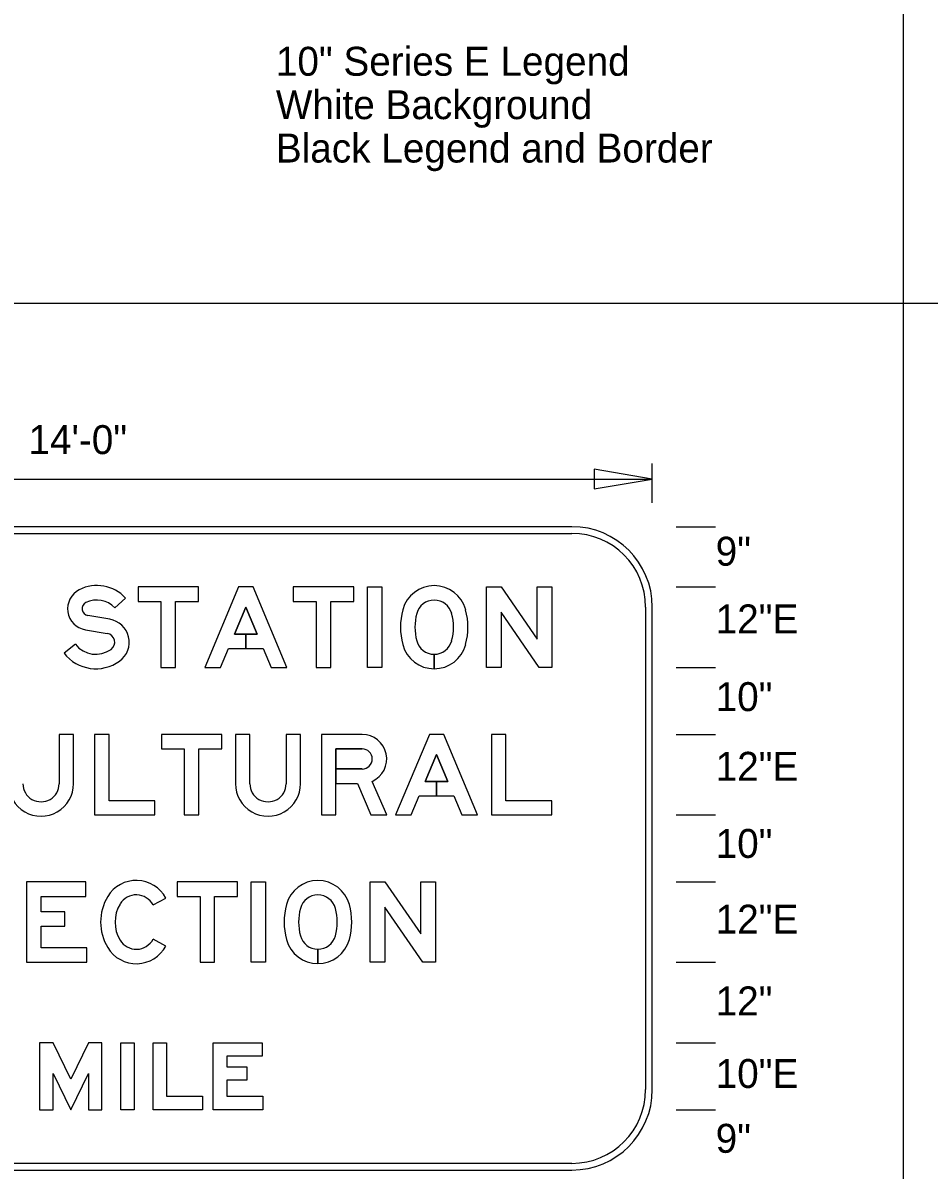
# Model space of a CAD drawing. Extents: x 0 to 770, y 0 to 495.
# Drawn here: x 86.3 to 195.9, y 225.2 to 363.9 of the extents above; entities that cross this region are included whole.
import ezdxf

# ---------------------------------------------------------------- set-up
doc = ezdxf.new("R2010")
doc.units = 0
for name, color, linetype in [('Dimension', 7, 'Continuous'), ('GSBWFill', 7, 'Continuous'), ('GSColorFill', 7, 'Continuous'), ('GSDims', 7, 'Continuous'), ('GSOutline', 7, 'Continuous'), ('SheetLines_dp', 7, 'Continuous'), ('TextStructures', 7, 'Continuous')]:
    doc.layers.add(name, color=color, linetype=linetype)

msp = doc.modelspace()

# ---------------------------------------------------------------- linework, layer by layer
at = {"layer": 'Dimension'}
msp.add_lwpolyline([(162.43, 308.76), (155.41, 309.95), (155.41, 307.57)], close=True, dxfattribs=at)
at = {"layer": 'GSBWFill'}
for p, q in [((152.7, 303.01), (35.95, 303.01)), ((152.7, 303.01), (35.95, 303.01)), ((35.95, 302.2), (152.7, 302.2)), ((97.47, 293.19), (98.75, 294.38)), ((161.62, 293.28), (161.62, 234.91)), ((162.43, 234.91), (162.43, 293.28)), ((162.43, 234.91), (162.43, 293.28)), ((96.84, 291.81), (94.19, 292.26)), ((93.89, 290.53), (96.54, 290.09)), ((92.69, 288.78), (91.31, 287.71)), ((136.06, 285.82), (136.06, 287.57)), ((136.06, 287.57), (136.06, 285.82)), ((90.72, 277.88), (90.72, 271.92)), ((118.16, 277.88), (118.16, 271.92)), ((102.07, 257.25), (103.61, 258.07)), ((103.61, 252.28), (102.07, 253.11)), ((102.07, 253.11), (102.07, 253.11)), ((122, 250.14), (122, 251.89)), ((122, 251.89), (122, 250.14)), ((35.95, 225.18), (152.7, 225.18)), ((152.7, 225.99), (35.96, 225.99)), ((35.96, 225.18), (152.7, 225.18))]:
    msp.add_line(p, q, dxfattribs=at)
for points in [[(100.26, 293.96), (103.03, 293.96), (103.03, 285.99), (104.78, 285.99), (104.78, 293.96), (107.55, 293.96), (107.55, 295.72), (100.26, 295.72)], [(114.66, 290.02), (113.3, 290.02), (113.3, 288.27), (115.4, 288.27), (116.36, 285.99), (118.26, 285.99), (114.17, 295.72), (112.42, 295.72), (108.33, 285.99), (110.23, 285.99), (111.19, 288.27), (113.29, 288.27), (113.29, 290.02), (111.93, 290.02), (113.29, 293.28)], [(119.03, 293.96), (121.81, 293.96), (121.81, 285.99), (123.56, 285.99), (123.56, 293.96), (126.33, 293.96), (126.33, 295.72), (119.03, 295.72)], [(127.99, 285.99), (127.99, 295.72), (129.74, 295.72), (129.74, 285.99)], [(150.27, 295.72), (150.27, 285.99), (148.76, 285.99), (144.14, 292.65), (144.14, 285.99), (142.38, 285.99), (142.38, 295.72), (144.14, 295.72), (148.51, 289.41), (148.51, 295.72)], [(102.3, 268.15), (102.3, 269.85), (96.76, 269.85), (96.76, 277.88), (95, 277.88), (95, 268.15)], [(103.08, 276.13), (105.85, 276.13), (105.85, 268.15), (107.6, 268.15), (107.6, 276.13), (110.38, 276.13), (110.38, 277.88), (103.08, 277.88)], [(137.72, 272.19), (136.35, 272.19), (136.35, 270.44), (138.45, 270.44), (139.41, 268.15), (141.31, 268.15), (137.23, 277.88), (135.48, 277.88), (131.39, 268.15), (133.29, 268.15), (134.25, 270.44), (136.35, 270.44), (136.35, 272.19), (134.99, 272.19), (136.35, 275.44)], [(150.27, 268.15), (150.27, 269.85), (144.72, 269.85), (144.72, 277.88), (142.97, 277.88), (142.97, 268.15)], [(94.08, 252.06), (88.53, 252.06), (88.53, 254.68), (91.4, 254.68), (91.4, 256.43), (88.53, 256.43), (88.53, 258.29), (93.93, 258.29), (93.93, 260.04), (86.78, 260.04), (86.78, 250.31), (94.08, 250.31)], [(104.98, 258.29), (107.75, 258.29), (107.75, 250.31), (109.5, 250.31), (109.5, 258.29), (112.27, 258.29), (112.27, 260.04), (104.98, 260.04)], [(113.93, 250.31), (113.93, 260.04), (115.68, 260.04), (115.68, 250.31)], [(136.21, 260.04), (136.21, 250.31), (134.7, 250.31), (130.08, 256.98), (130.08, 250.31), (128.33, 250.31), (128.33, 260.04), (130.08, 260.04), (134.46, 253.74), (134.46, 260.04)], [(94.28, 236.88), (94.28, 232.48), (95.9, 232.48), (95.9, 240.58), (94.28, 240.58), (92.13, 236.18), (89.99, 240.58), (88.36, 240.58), (88.36, 232.48), (89.99, 232.48), (89.99, 236.88), (92.13, 232.48)], [(98.17, 240.58), (99.8, 240.58), (99.8, 232.48), (98.17, 232.48)], [(103.69, 234.1), (108.07, 234.1), (108.07, 232.48), (102.07, 232.48), (102.07, 240.58), (103.69, 240.58)], [(115.28, 240.58), (115.28, 238.96), (110.98, 238.96), (110.98, 237.67), (113.42, 237.67), (113.42, 236.04), (110.98, 236.04), (110.98, 234.1), (115.36, 234.1), (115.36, 232.48), (109.36, 232.48), (109.36, 240.58)]]:
    msp.add_lwpolyline(points, close=True, dxfattribs=at)
for points in [[(92.47, 271.92), (92.47, 277.88), (90.72, 277.88)], [(113.78, 271.92), (113.78, 277.88), (112.03, 277.88), (112.03, 271.92)], [(119.91, 271.92), (119.91, 277.88), (118.16, 277.88)], [(127.35, 277.88), (122.44, 277.88), (122.44, 268.15), (124.19, 268.15), (124.19, 276.13), (127.35, 276.13)], [(127.35, 273.7), (124.19, 273.7), (124.19, 271.94)], [(124.19, 271.94), (126.77, 271.94), (128.41, 268.15), (130.32, 268.15), (128.57, 272.2)]]:
    msp.add_lwpolyline(points, dxfattribs=at)
for centre, radius, start, end in [((152.7, 293.28), 9.73, 0, 90), ((152.7, 293.28), 9.73, 0, 90), ((152.7, 293.28), 8.92, 0, 90), ((95.29, 291.17), 4.72, 42.8759, 116.9123), ((94.32, 293.08), 2.58, 116.9123, 260.4087), ((94.32, 293.08), 0.827, 116.9123, 260.4087), ((95.29, 291.17), 2.97, 42.8759, 116.9123), ((96.37, 289.03), 2.82, 306.123, 80.4087), ((96.37, 289.03), 1.07, 306.123, 80.4087), ((95.16, 290.68), 3.11, 217.5895, 306.123), ((95.16, 290.68), 4.86, 217.5895, 306.123), ((122, 256.27), 3.94, 14.9618, 165.0382), ((122, 256.27), 2.19, 14.9618, 165.0382), ((126.09, 255.18), 8.17, 165.0382, 194.9618), ((126.09, 255.18), 6.42, 165.0382, 194.9618), ((117.92, 255.18), 6.42, 345.0382, 14.9618), ((117.92, 255.18), 8.17, 345.0382, 14.9618), ((122, 254.09), 3.94, 194.9618, 270), ((122, 254.09), 2.19, 194.9618, 270), ((122, 254.09), 2.19, 270.0127, 345.0382), ((122, 254.09), 3.94, 270.0071, 345.0382), ((152.7, 234.91), 9.73, 270, 0), ((152.7, 234.91), 8.92, 270, 0), ((152.7, 234.91), 9.73, 270, 0)]:
    msp.add_arc(centre, radius, start, end, dxfattribs=at)
for centre, major_axis, start_param, end_param in [((136.06, 291.94), (0, 3.94), 4.973521, 7.592849), ((140.15, 290.85), (0, 8.17), 1.309664, 1.831929), ((136.06, 291.94), (0, 2.19), 4.973521, 7.592849), ((131.97, 290.85), (0, 8.17), 4.451257, 4.973521), ((140.15, 290.85), (0, 6.42), 1.309664, 1.831929), ((131.97, 290.85), (0, 6.42), 4.451257, 4.973521), ((136.06, 289.76), (0, 3.94), 1.831929, 3.141593), ((136.06, 289.76), (0, 2.19), 1.831929, 3.141593), ((136.06, 289.76), (0, 2.19), 3.141815, 4.451257), ((136.06, 289.76), (0, 3.94), 3.141716, 4.451257), ((127.35, 274.91), (0, 2.97), 3.562504, 6.283185), ((127.35, 274.91), (0, 1.22), 3.141593, 6.283185), ((88.53, 271.92), (0, 3.94), 1.570796, 4.712389), ((88.53, 271.92), (0, 2.19), 1.570796, 4.712389), ((115.97, 271.92), (0, 3.94), 1.570796, 4.712389), ((115.97, 271.92), (0, 2.19), 1.570796, 4.712389), ((100.05, 256.18), (0, 4.04), 5.201543, 7.308565), ((101.69, 255.18), (0, 5.96), 1.025379, 2.116213), ((100.05, 256.18), (0, 2.29), 5.201543, 7.308565), ((101.69, 255.18), (0, 4.21), 1.025379, 2.116213), ((100.05, 254.18), (0, 2.29), 2.116213, 4.223235), ((100.05, 254.18), (0, 4.04), 2.116213, 4.223235)]:
    msp.add_ellipse(centre, major_axis=major_axis, ratio=0.999994, start_param=start_param, end_param=end_param, dxfattribs=at)
at = {"layer": 'GSColorFill'}
for p, q in [((97.47, 293.19), (98.75, 294.38)), ((96.84, 291.81), (94.19, 292.26)), ((93.89, 290.53), (96.54, 290.09)), ((92.69, 288.78), (91.31, 287.71)), ((136.06, 285.82), (136.06, 287.57)), ((136.06, 287.57), (136.06, 285.82)), ((90.72, 277.88), (90.72, 271.92)), ((118.16, 277.88), (118.16, 271.92)), ((102.07, 257.25), (103.61, 258.07)), ((103.61, 252.28), (102.07, 253.11)), ((102.07, 253.11), (102.07, 253.11)), ((122, 250.14), (122, 251.89)), ((122, 251.89), (122, 250.14))]:
    msp.add_line(p, q, dxfattribs=at)
for points in [[(100.26, 293.96), (103.03, 293.96), (103.03, 285.99), (104.78, 285.99), (104.78, 293.96), (107.55, 293.96), (107.55, 295.72), (100.26, 295.72)], [(114.66, 290.02), (113.3, 290.02), (113.3, 288.27), (115.4, 288.27), (116.36, 285.99), (118.26, 285.99), (114.17, 295.72), (112.42, 295.72), (108.33, 285.99), (110.23, 285.99), (111.19, 288.27), (113.29, 288.27), (113.29, 290.02), (111.93, 290.02), (113.29, 293.28)], [(119.03, 293.96), (121.81, 293.96), (121.81, 285.99), (123.56, 285.99), (123.56, 293.96), (126.33, 293.96), (126.33, 295.72), (119.03, 295.72)], [(127.99, 285.99), (127.99, 295.72), (129.74, 295.72), (129.74, 285.99)], [(150.27, 295.72), (150.27, 285.99), (148.76, 285.99), (144.14, 292.65), (144.14, 285.99), (142.38, 285.99), (142.38, 295.72), (144.14, 295.72), (148.51, 289.41), (148.51, 295.72)], [(102.3, 268.15), (102.3, 269.85), (96.76, 269.85), (96.76, 277.88), (95, 277.88), (95, 268.15)], [(103.08, 276.13), (105.85, 276.13), (105.85, 268.15), (107.6, 268.15), (107.6, 276.13), (110.38, 276.13), (110.38, 277.88), (103.08, 277.88)], [(137.72, 272.19), (136.35, 272.19), (136.35, 270.44), (138.45, 270.44), (139.41, 268.15), (141.31, 268.15), (137.23, 277.88), (135.48, 277.88), (131.39, 268.15), (133.29, 268.15), (134.25, 270.44), (136.35, 270.44), (136.35, 272.19), (134.99, 272.19), (136.35, 275.44)], [(150.27, 268.15), (150.27, 269.85), (144.72, 269.85), (144.72, 277.88), (142.97, 277.88), (142.97, 268.15)], [(94.08, 252.06), (88.53, 252.06), (88.53, 254.68), (91.4, 254.68), (91.4, 256.43), (88.53, 256.43), (88.53, 258.29), (93.93, 258.29), (93.93, 260.04), (86.78, 260.04), (86.78, 250.31), (94.08, 250.31)], [(104.98, 258.29), (107.75, 258.29), (107.75, 250.31), (109.5, 250.31), (109.5, 258.29), (112.27, 258.29), (112.27, 260.04), (104.98, 260.04)], [(113.93, 250.31), (113.93, 260.04), (115.68, 260.04), (115.68, 250.31)], [(136.21, 260.04), (136.21, 250.31), (134.7, 250.31), (130.08, 256.98), (130.08, 250.31), (128.33, 250.31), (128.33, 260.04), (130.08, 260.04), (134.46, 253.74), (134.46, 260.04)], [(94.28, 236.88), (94.28, 232.48), (95.9, 232.48), (95.9, 240.58), (94.28, 240.58), (92.13, 236.18), (89.99, 240.58), (88.36, 240.58), (88.36, 232.48), (89.99, 232.48), (89.99, 236.88), (92.13, 232.48)], [(98.17, 240.58), (99.8, 240.58), (99.8, 232.48), (98.17, 232.48)], [(103.69, 234.1), (108.07, 234.1), (108.07, 232.48), (102.07, 232.48), (102.07, 240.58), (103.69, 240.58)], [(115.28, 240.58), (115.28, 238.96), (110.98, 238.96), (110.98, 237.67), (113.42, 237.67), (113.42, 236.04), (110.98, 236.04), (110.98, 234.1), (115.36, 234.1), (115.36, 232.48), (109.36, 232.48), (109.36, 240.58)]]:
    msp.add_lwpolyline(points, close=True, dxfattribs=at)
for points in [[(92.47, 271.92), (92.47, 277.88), (90.72, 277.88)], [(113.78, 271.92), (113.78, 277.88), (112.03, 277.88), (112.03, 271.92)], [(119.91, 271.92), (119.91, 277.88), (118.16, 277.88)], [(127.35, 277.88), (122.44, 277.88), (122.44, 268.15), (124.19, 268.15), (124.19, 276.13), (127.35, 276.13)], [(127.35, 273.7), (124.19, 273.7), (124.19, 271.94)], [(124.19, 271.94), (126.77, 271.94), (128.41, 268.15), (130.32, 268.15), (128.57, 272.2)]]:
    msp.add_lwpolyline(points, dxfattribs=at)
for centre, radius, start, end in [((95.29, 291.17), 4.72, 42.8759, 116.9123), ((94.32, 293.08), 2.58, 116.9123, 260.4087), ((94.32, 293.08), 0.827, 116.9123, 260.4087), ((95.29, 291.17), 2.97, 42.8759, 116.9123), ((96.37, 289.03), 2.82, 306.123, 80.4087), ((96.37, 289.03), 1.07, 306.123, 80.4087), ((95.16, 290.68), 3.11, 217.5895, 306.123), ((95.16, 290.68), 4.86, 217.5895, 306.123), ((122, 256.27), 3.94, 14.9618, 165.0382), ((122, 256.27), 2.19, 14.9618, 165.0382), ((126.09, 255.18), 8.17, 165.0382, 194.9618), ((126.09, 255.18), 6.42, 165.0382, 194.9618), ((117.92, 255.18), 6.42, 345.0382, 14.9618), ((117.92, 255.18), 8.17, 345.0382, 14.9618), ((122, 254.09), 3.94, 194.9618, 270), ((122, 254.09), 2.19, 194.9618, 270), ((122, 254.09), 2.19, 270.0127, 345.0382), ((122, 254.09), 3.94, 270.0071, 345.0382)]:
    msp.add_arc(centre, radius, start, end, dxfattribs=at)
for centre, major_axis, start_param, end_param in [((136.06, 291.94), (0, 3.94), 4.973521, 7.592849), ((140.15, 290.85), (0, 8.17), 1.309664, 1.831929), ((136.06, 291.94), (0, 2.19), 4.973521, 7.592849), ((131.97, 290.85), (0, 8.17), 4.451257, 4.973521), ((140.15, 290.85), (0, 6.42), 1.309664, 1.831929), ((131.97, 290.85), (0, 6.42), 4.451257, 4.973521), ((136.06, 289.76), (0, 3.94), 1.831929, 3.141593), ((136.06, 289.76), (0, 2.19), 1.831929, 3.141593), ((136.06, 289.76), (0, 2.19), 3.141815, 4.451257), ((136.06, 289.76), (0, 3.94), 3.141716, 4.451257), ((127.35, 274.91), (0, 2.97), 3.562504, 6.283185), ((127.35, 274.91), (0, 1.22), 3.141593, 6.283185), ((88.53, 271.92), (0, 3.94), 1.570796, 4.712389), ((88.53, 271.92), (0, 2.19), 1.570796, 4.712389), ((115.97, 271.92), (0, 3.94), 1.570796, 4.712389), ((115.97, 271.92), (0, 2.19), 1.570796, 4.712389), ((100.05, 256.18), (0, 4.04), 5.201543, 7.308565), ((101.69, 255.18), (0, 5.96), 1.025379, 2.116213), ((100.05, 256.18), (0, 2.29), 5.201543, 7.308565), ((101.69, 255.18), (0, 4.21), 1.025379, 2.116213), ((100.05, 254.18), (0, 2.29), 2.116213, 4.223235), ((100.05, 254.18), (0, 4.04), 2.116213, 4.223235)]:
    msp.add_ellipse(centre, major_axis=major_axis, ratio=0.999994, start_param=start_param, end_param=end_param, dxfattribs=at)
at = {"layer": 'GSDims'}
for p, q in [((162.43, 305.89), (162.43, 310.67)), ((26.22, 308.76), (162.43, 308.76)), ((165.3, 303.01), (170.09, 303.01)), ((165.3, 295.72), (170.09, 295.72)), ((165.3, 295.72), (170.09, 295.72)), ((165.3, 285.99), (170.09, 285.99)), ((165.3, 285.99), (170.09, 285.99)), ((165.3, 277.88), (170.09, 277.88)), ((165.3, 277.88), (170.09, 277.88)), ((165.3, 268.15), (170.09, 268.15)), ((165.3, 268.15), (170.09, 268.15)), ((165.3, 260.04), (170.09, 260.04)), ((165.3, 260.04), (170.09, 260.04)), ((165.3, 250.31), (170.09, 250.31)), ((165.3, 250.31), (170.09, 250.31)), ((165.3, 240.58), (170.09, 240.58)), ((165.3, 240.58), (170.09, 240.58)), ((165.3, 232.48), (170.09, 232.48)), ((165.3, 232.48), (170.09, 232.48))]:
    msp.add_line(p, q, dxfattribs=at)
at = {"layer": 'GSOutline'}
for p, q in [((97.47, 293.19), (98.75, 294.38)), ((96.84, 291.81), (94.19, 292.26)), ((93.89, 290.53), (96.54, 290.09)), ((92.69, 288.78), (91.31, 287.71)), ((90.72, 277.88), (90.72, 271.92)), ((118.16, 277.88), (118.16, 271.92)), ((124.19, 273.7), (127.35, 273.7)), ((102.07, 257.25), (103.61, 258.07)), ((103.61, 252.28), (102.07, 253.11)), ((102.07, 253.11), (102.07, 253.11))]:
    msp.add_line(p, q, dxfattribs=at)
for points in [[(100.26, 293.96), (103.03, 293.96), (103.03, 285.99), (104.78, 285.99), (104.78, 293.96), (107.55, 293.96), (107.55, 295.72), (100.26, 295.72)], [(111.19, 288.27), (115.4, 288.27), (116.36, 285.99), (118.26, 285.99), (114.17, 295.72), (112.42, 295.72), (108.33, 285.99), (110.23, 285.99)], [(119.03, 293.96), (121.81, 293.96), (121.81, 285.99), (123.56, 285.99), (123.56, 293.96), (126.33, 293.96), (126.33, 295.72), (119.03, 295.72)], [(127.99, 285.99), (127.99, 295.72), (129.74, 295.72), (129.74, 285.99)], [(150.27, 295.72), (150.27, 285.99), (148.76, 285.99), (144.14, 292.65), (144.14, 285.99), (142.38, 285.99), (142.38, 295.72), (144.14, 295.72), (148.51, 289.41), (148.51, 295.72)], [(114.66, 290.02), (113.29, 293.28), (111.93, 290.02)], [(102.3, 268.15), (102.3, 269.85), (96.76, 269.85), (96.76, 277.88), (95, 277.88), (95, 268.15)], [(103.08, 276.13), (105.85, 276.13), (105.85, 268.15), (107.6, 268.15), (107.6, 276.13), (110.38, 276.13), (110.38, 277.88), (103.08, 277.88)], [(134.25, 270.44), (138.45, 270.44), (139.41, 268.15), (141.31, 268.15), (137.23, 277.88), (135.48, 277.88), (131.39, 268.15), (133.29, 268.15)], [(150.27, 268.15), (150.27, 269.85), (144.72, 269.85), (144.72, 277.88), (142.97, 277.88), (142.97, 268.15)], [(137.72, 272.19), (136.35, 275.44), (134.99, 272.19)], [(94.08, 252.06), (88.53, 252.06), (88.53, 254.68), (91.4, 254.68), (91.4, 256.43), (88.53, 256.43), (88.53, 258.29), (93.93, 258.29), (93.93, 260.04), (86.78, 260.04), (86.78, 250.31), (94.08, 250.31)], [(104.98, 258.29), (107.75, 258.29), (107.75, 250.31), (109.5, 250.31), (109.5, 258.29), (112.27, 258.29), (112.27, 260.04), (104.98, 260.04)], [(113.93, 250.31), (113.93, 260.04), (115.68, 260.04), (115.68, 250.31)], [(136.21, 260.04), (136.21, 250.31), (134.7, 250.31), (130.08, 256.98), (130.08, 250.31), (128.33, 250.31), (128.33, 260.04), (130.08, 260.04), (134.46, 253.74), (134.46, 260.04)], [(94.28, 236.88), (94.28, 232.48), (95.9, 232.48), (95.9, 240.58), (94.28, 240.58), (92.13, 236.18), (89.99, 240.58), (88.36, 240.58), (88.36, 232.48), (89.99, 232.48), (89.99, 236.88), (92.13, 232.48)], [(98.17, 240.58), (99.8, 240.58), (99.8, 232.48), (98.17, 232.48)], [(103.69, 234.1), (108.07, 234.1), (108.07, 232.48), (102.07, 232.48), (102.07, 240.58), (103.69, 240.58)], [(115.28, 240.58), (115.28, 238.96), (110.98, 238.96), (110.98, 237.67), (113.42, 237.67), (113.42, 236.04), (110.98, 236.04), (110.98, 234.1), (115.36, 234.1), (115.36, 232.48), (109.36, 232.48), (109.36, 240.58)]]:
    msp.add_lwpolyline(points, close=True, dxfattribs=at)
for points in [[(92.47, 271.92), (92.47, 277.88), (90.72, 277.88)], [(113.78, 271.92), (113.78, 277.88), (112.03, 277.88), (112.03, 271.92)], [(119.91, 271.92), (119.91, 277.88), (118.16, 277.88)], [(127.35, 277.88), (122.44, 277.88), (122.44, 268.15), (124.19, 268.15), (124.19, 271.94), (126.77, 271.94)], [(127.35, 276.13), (124.19, 276.13), (124.19, 273.7)], [(126.77, 271.94), (128.41, 268.15), (130.32, 268.15), (128.57, 272.2)]]:
    msp.add_lwpolyline(points, dxfattribs=at)
for centre, radius, start, end in [((95.29, 291.17), 4.72, 42.8759, 116.9123), ((94.32, 293.08), 2.58, 116.9123, 260.4087), ((94.32, 293.08), 0.827, 116.9123, 260.4087), ((95.29, 291.17), 2.97, 42.8759, 116.9123), ((96.37, 289.03), 2.82, 306.123, 80.4087), ((96.37, 289.03), 1.07, 306.123, 80.4087), ((95.16, 290.68), 3.11, 217.5895, 306.123), ((95.16, 290.68), 4.86, 217.5895, 306.123), ((122, 256.27), 3.94, 14.9618, 165.0382), ((122, 256.27), 2.19, 14.9618, 165.0382), ((126.09, 255.18), 8.17, 165.0382, 194.9618), ((126.09, 255.18), 6.42, 165.0382, 194.9618), ((117.92, 255.18), 6.42, 345.0382, 14.9618), ((117.92, 255.18), 8.17, 345.0382, 14.9618), ((122, 254.09), 3.94, 194.9618, 345.0382), ((122, 254.09), 2.19, 194.9618, 345.0382)]:
    msp.add_arc(centre, radius, start, end, dxfattribs=at)
for centre, major_axis, start_param, end_param in [((136.06, 291.94), (0, 3.94), 4.973521, 7.592849), ((140.15, 290.85), (0, 8.17), 1.309664, 1.831929), ((136.06, 291.94), (0, 2.19), 4.973521, 7.592849), ((131.97, 290.85), (0, 8.17), 4.451257, 4.973521), ((140.15, 290.85), (0, 6.42), 1.309664, 1.831929), ((131.97, 290.85), (0, 6.42), 4.451257, 4.973521), ((136.06, 289.76), (0, 3.94), 1.831929, 4.451257), ((136.06, 289.76), (0, 2.19), 1.831929, 4.451257), ((127.35, 274.91), (0, 2.97), 3.562504, 6.283185), ((127.35, 274.91), (0, 1.22), 3.141593, 6.283185), ((88.53, 271.92), (0, 3.94), 1.570796, 4.712389), ((88.53, 271.92), (0, 2.19), 1.570796, 4.712389), ((115.97, 271.92), (0, 3.94), 1.570796, 4.712389), ((115.97, 271.92), (0, 2.19), 1.570796, 4.712389), ((100.05, 256.18), (0, 4.04), 5.201543, 7.308565), ((101.69, 255.18), (0, 5.96), 1.025379, 2.116213), ((100.05, 256.18), (0, 2.29), 5.201543, 7.308565), ((101.69, 255.18), (0, 4.21), 1.025379, 2.116213), ((100.05, 254.18), (0, 2.29), 2.116213, 4.223235), ((100.05, 254.18), (0, 4.04), 2.116213, 4.223235)]:
    msp.add_ellipse(centre, major_axis=major_axis, ratio=0.999994, start_param=start_param, end_param=end_param, dxfattribs=at)
at = {"layer": 'SheetLines_dp'}
for p, q in [((192.8, 0), (192.8, 495)), ((770, 330), (0, 330))]:
    msp.add_line(p, q, dxfattribs=at)

# ---------------------------------------------------------------- texts
at = {"layer": 'TextStructures'}
for s, p in [('10" Series E Legend', (116.92, 357.56)), ('White Background', (116.92, 352.31)), ('Black Legend and Border', (116.92, 347.06)), ('14\'-0"', (87.01, 311.79)), ('9"', (170.09, 298.29)), ('12"E', (170.09, 290.1)), ('10"', (170.09, 280.7)), ('12"E', (170.09, 272.27)), ('10"', (170.09, 262.94)), ('12"E', (170.09, 253.78)), ('12"', (170.09, 243.89)), ('10"E', (170.09, 235.11)), ('9"', (170.09, 227.27))]:
    msp.add_text(s, height=3.5, dxfattribs=at).set_placement(p)

doc.saveas('drawing.dxf')
